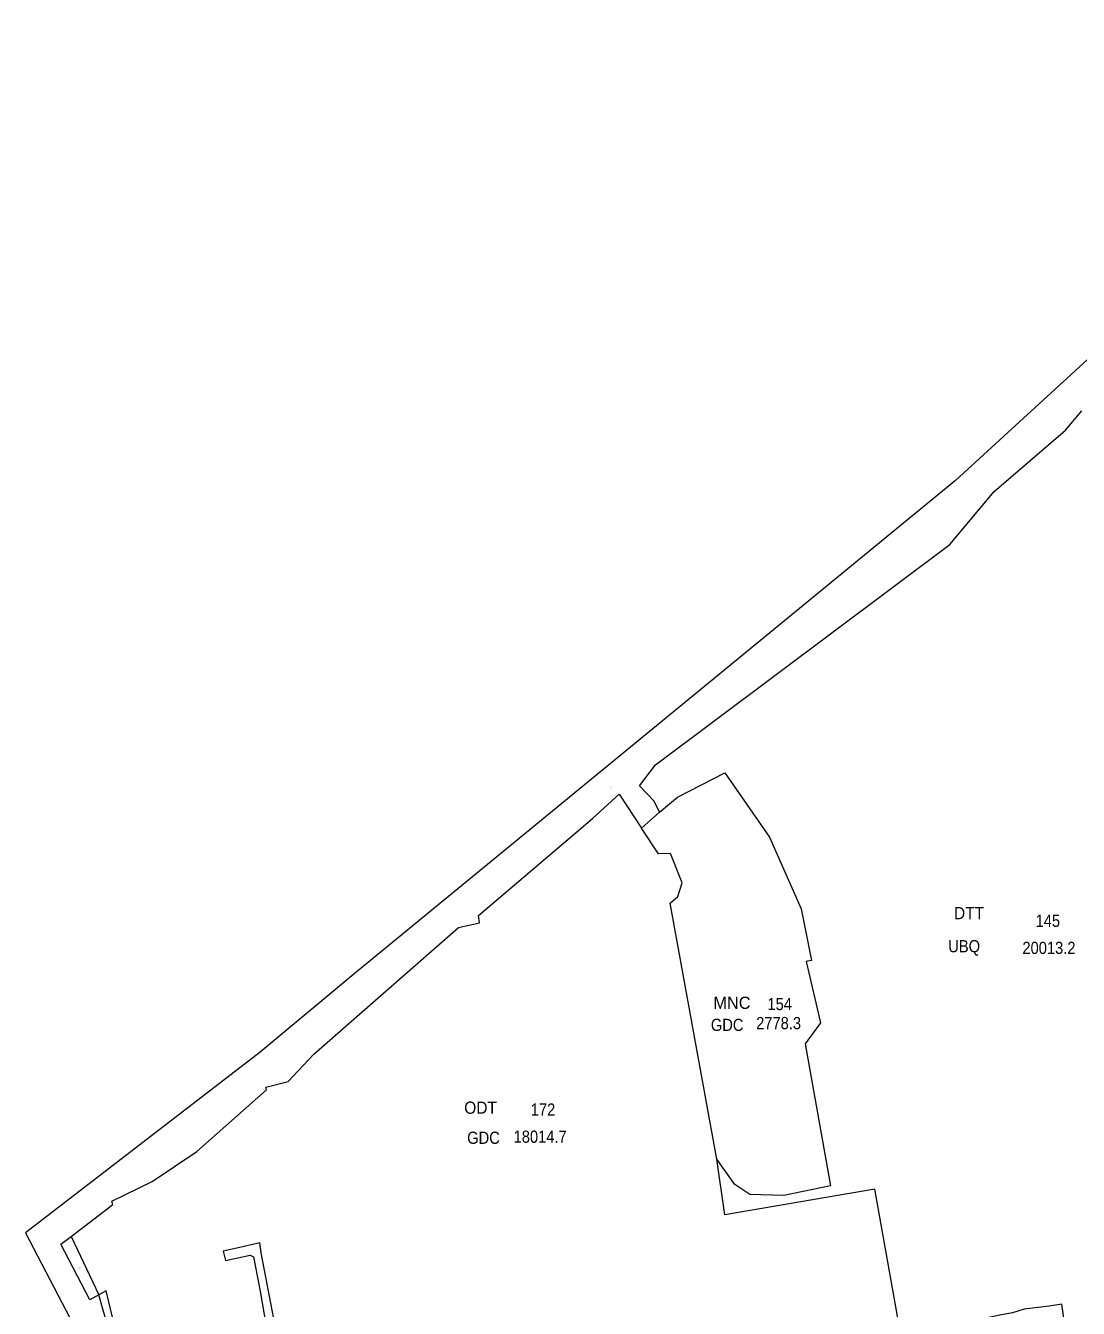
# Model space of a CAD drawing. Extents: x 588385 to 589522, y 2273243 to 2275031.
# Drawn here: x 588384.8 to 588643.5, y 2274106.4 to 2274421.5 of the extents above; entities that cross this region are included whole.
import ezdxf
from ezdxf.enums import TextEntityAlignment as Align

# ---------------------------------------------------------------- set-up
doc = ezdxf.new("R2010")
doc.units = 0
doc.header["$LTSCALE"] = 0.04
doc.layers.add('10', color=7, linetype='Continuous', lineweight=13)
for name, color, linetype in [('33', 7, 'Continuous'), ('35', 7, 'Continuous'), ('54', 7, 'Continuous'), ('60', 7, 'Continuous')]:
    doc.layers.add(name, color=color, linetype=linetype)

msp = doc.modelspace()

# ---------------------------------------------------------------- linework, layer by layer
at = {"layer": '10'}
for p, q in [((588536.14, 2274224.32), (588540.51, 2274228.28)), ((588395.95, 2274124.03), (588402.75, 2274109.67)), ((588404.89, 2274102.19), (588402.75, 2274109.67))]:
    msp.add_line(p, q, dxfattribs=at)
for points in [[(588743.32, 2274423.51), (588745.46, 2274420.97), (588737.86, 2274414.85), (588734.47, 2274412.12), (588731.43, 2274409.47), (588711.87, 2274393.1), (588648.58, 2274342.09), (588613.3, 2274309.8), (588465.41, 2274188.5), (588442.4, 2274169.28), (588384.76, 2274124.94), (588398.65, 2274098.19), (588405, 2274082.42), (588410.29, 2274057.53), (588414.22, 2274044.57), (588440.78, 2273955.92), (588445.12, 2273956.59), (588445.1, 2273956.67), (588454.87, 2273958.13), (588455.87, 2273958.38)], [(588540.51, 2274228.28), (588539.19, 2274230.98), (588535.65, 2274234.71), (588539.58, 2274239.94), (588611.86, 2274294.06), (588622.81, 2274307.1), (588640.31, 2274322.16), (588644.36, 2274326.86)], [(588540.51, 2274228.28), (588544.95, 2274231.94), (588556.58, 2274237.94), (588567.54, 2274222.16), (588575.34, 2274204.5), (588577.88, 2274191.85), (588576.57, 2274191.61), (588580.13, 2274176.54), (588576.38, 2274171.39), (588582.6, 2274136.44), (588571.09, 2274134.09), (588562.75, 2274134.36), (588559.08, 2274136.77), (588554.65, 2274143.05)], [(588395.95, 2274124.03), (588406.2, 2274131.9), (588405.96, 2274132.66), (588415.85, 2274137.56), (588426.8, 2274144.93), (588443.92, 2274160.07), (588443.78, 2274160.69), (588449.29, 2274162.11), (588455.62, 2274168.83), (588491.11, 2274199.95), (588496.32, 2274201.1), (588496.06, 2274202.9), (588524.08, 2274226.72), (588530.63, 2274232.68), (588536.14, 2274224.32)], [(588554.65, 2274143.05), (588543.14, 2274205.92), (588545.04, 2274207.54), (588546.14, 2274210.95), (588543.26, 2274218.15), (588540.28, 2274218.03), (588536.14, 2274224.32)], [(588640.86, 2274097.01), (588639.39, 2274107.36), (588636.27, 2274106.91), (588630.2, 2274106.18), (588627.27, 2274105.26), (588624.15, 2274104.65), (588621.03, 2274104.01), (588618.05, 2274103.45), (588614.93, 2274102.93), (588611.88, 2274102.28), (588608.93, 2274101.7), (588605.89, 2274100.95), (588602.62, 2274100.42), (588599.87, 2274099.89), (588593.43, 2274135.61), (588556.6, 2274129.32), (588554.65, 2274143.05)], [(588402.75, 2274109.67), (588400.5, 2274108.45), (588393.43, 2274122.1), (588395.95, 2274124.03)], [(588447.84, 2274093.18), (588442.64, 2274119.97), (588442.28, 2274122.43), (588436.63, 2274121.11), (588433.33, 2274120.4), (588433.86, 2274118.12), (588439.98, 2274119.39), (588440.74, 2274119), (588442.41, 2274110.58), (588444.36, 2274099.11)], [(588406.18, 2274103.88), (588404.51, 2274110.63), (588402.75, 2274109.67)]]:
    msp.add_lwpolyline(points, dxfattribs=at)

# ---------------------------------------------------------------- texts
at = {"layer": '33'}
for s, height, width, p in [('DTL', 0.1, 0.95, (588528.62, 2274234.61)), ('DTT', 3, 0.95, (588620.32, 2274201.97)), ('ODT', 3, 0.95, (588500.59, 2274154.17)), ('BCS', 0.1, 0.85, (588397.99, 2274116.24))]:
    msp.add_text(s, height=height, dxfattribs=dict(at, width=width)).set_placement(p, align=Align.RIGHT)
msp.add_text('MNC', height=3, dxfattribs=at).set_placement((588562.92, 2274179.94), align=Align.RIGHT)
at = {"layer": '35', "width": 0.9}
for s, height, p in [('137', 0.1, (588528.97, 2274234.61)), ('145', 3, (588638.99, 2274200.09)), ('154', 3, (588573.09, 2274179.64)), ('172', 3, (588514.92, 2274153.71)), ('189', 0.1, (588398.26, 2274116.24))]:
    msp.add_text(s, height=height, dxfattribs=at).set_placement(p, align=Align.RIGHT)
at = {"layer": '54'}
for s, height, width, p in [('7377.6', 0.1, 0.85, (588528.97, 2274234.41)), ('20013.2', 3, 0.9, (588642.78, 2274193.43)), ('2778.3', 3, 0.9, (588575.33, 2274174.95)), ('18014.7', 3, 0.9, (588517.73, 2274147.04)), ('44.3', 0.1, 0.9, (588398.26, 2274116.04))]:
    msp.add_text(s, height=height, dxfattribs=dict(at, width=width)).set_placement(p, align=Align.RIGHT)
at = {"layer": '60', "width": 0.9}
for s, height, p in [('UBQ', 0.1, (588528.58, 2274234.39)), ('UBQ', 3, (588619.33, 2274193.84)), ('GDC', 3, (588561.18, 2274174.51)), ('GDC', 3, (588501.3, 2274146.78)), ('UBQ', 0.1, (588398, 2274116.04))]:
    msp.add_text(s, height=height, dxfattribs=at).set_placement(p, align=Align.RIGHT)

doc.saveas('drawing.dxf')
